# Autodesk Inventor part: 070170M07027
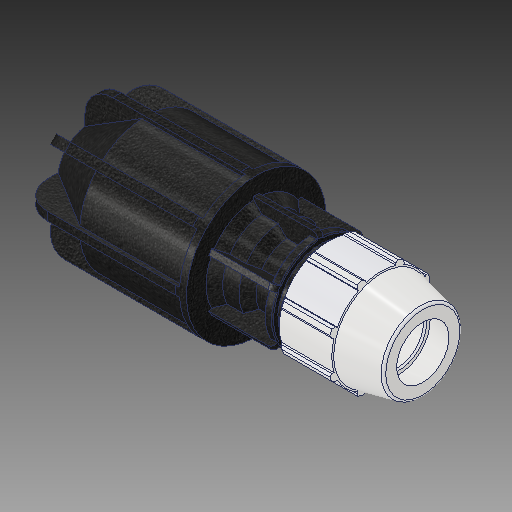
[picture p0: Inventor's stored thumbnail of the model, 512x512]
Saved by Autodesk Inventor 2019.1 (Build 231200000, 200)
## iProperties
Created: 2017-02
Part Number: 070170M07027
Material: PVC-Piping
Description: PLASSON PLASS4 COUPLING 3/4'' - 0.925
Document SubType Name: Modeling
Designer: KIM
Mass: 92.6774 g
Surface Area: 199.44 cm^2
Volume: 66.1981 cm^3
Density: 1.4 g/cm^3
Appearance: PTFE
Author: KIM
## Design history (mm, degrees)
derived "070170M0.ipt"
feature "Solid1::070170M0.ipt"
tag "TaggingFeature1"
body "Solid1"
other parameters: "d_" = 26.6, "E_" = 54.102, "A_" = 81, "l_" = 59.944, "d_1" = 23.495, "E_1" = 71.12, "l_1" = 85.09, "H_" = 169.926, "d106" = 33.99789, "d2" = 26.6, "d4" = 12.13757, "d5" = 20.9804, "d7" = 54.102, "d8" = 33.99789, "d9" = 11.57143, "d11" = 4.24815, "d12" = 43.2816, "d13" = 120 deg, "d14" = 39.9, "d15" = 12 deg, "d16" = 48.6918, "d18" = 1.33, "d19" = 35 deg, "d20" = 17.5 deg, "d21" = 50.31486, "d23" = 0, "d25" = 360 deg, "d27" = 1.08204, "d42" = 26.9748, "d43" = 1.62306, "d46" = 0.798, "d53" = 0.532, "d67" = 2.7051, "d70" = 23.94, "d71" = 59.944, "d74" = 180 deg, "d75" = 23.495, "d76" = 71.12, "d80" = 23.94, "d84" = 67.564, "d85" = 135 deg, "d86" = 3.556, "d89" = 3.556, "d90" = 135 deg, "d94" = 3.556, "d97" = 4.32816, "d98" = 0, "d100" = 360 deg, "d102" = 78.232, "d103" = 14.224, "d104" = 5.6896, "d105" = 0, "d110" = 85.09, "d112" = 101.9556, "d113" = 28.9306, "d114" = 67.9704, "d115" = 42.672, "d116" = 101.9556, "d117" = 4.2545, "d118" = 27.051, "d119" = 2.7051, "d120" = 0, "d121" = 2.7051, "d123" = 360 deg
